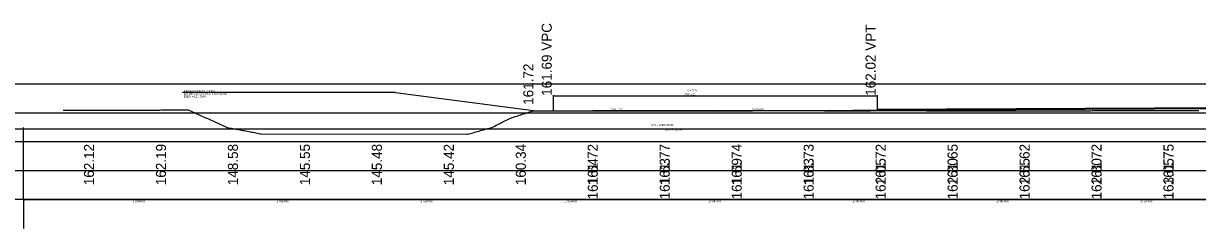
# Model space of a CAD drawing. Extents: x 2126510 to 2136144, y 865066 to 868066.
# Drawn here: x 2131523 to 2132339, y 867794 to 867936 of the extents above; entities that cross this region are included whole.
import ezdxf

# ---------------------------------------------------------------- set-up
doc = ezdxf.new("R2010")
doc.units = 0
for name, color, linetype in [('RD_EX_GuardRail', 7, 'Continuous'), ('RD_EX_H2O', 7, 'Continuous'), ('RD_EX_Misc', 7, 'Continuous'), ('RD_EX_UT', 7, 'Continuous')]:
    doc.layers.add(name, color=color, linetype=linetype)

msp = doc.modelspace()

# ---------------------------------------------------------------- linework, layer by layer
at = {"layer": 'RD_EX_GuardRail'}
for p, q in [((2135251.98, 867894.32), (2130671.73, 867894.32)), ((2133154.24, 867874.32), (2130671.73, 867874.32)), ((2135251.98, 867854.32), (2130671.73, 867854.32)), ((2135251.98, 867834.32), (2130671.73, 867834.32)), ((2135251.98, 867814.32), (2130671.73, 867814.32))]:
    msp.add_line(p, q, dxfattribs=at)
at = {"layer": 'RD_EX_H2O'}
for points in [[(2131550.47, 867876.38), (2131551.47, 867876.38), (2131552.47, 867876.38), (2131553.47, 867876.38), (2131554.47, 867876.38), (2131555.47, 867876.38), (2131556.47, 867876.38), (2131557.47, 867876.38), (2131558.47, 867876.38), (2131559.47, 867876.38), (2131560.47, 867876.38), (2131561.47, 867876.39), (2131562.47, 867876.39), (2131563.47, 867876.4), (2131564.47, 867876.4), (2131565.47, 867876.41), (2131566.47, 867876.41), (2131567.47, 867876.41), (2131568.47, 867876.42), (2131569.47, 867876.42), (2131570.47, 867876.43), (2131571.47, 867876.43), (2131572.47, 867876.44), (2131573.47, 867876.44), (2131574.47, 867876.45), (2131575.47, 867876.45), (2131576.47, 867876.45), (2131577.47, 867876.46), (2131578.47, 867876.46), (2131579.47, 867876.46), (2131580.47, 867876.46), (2131581.47, 867876.46), (2131582.47, 867876.46), (2131583.47, 867876.46), (2131584.47, 867876.46), (2131585.47, 867876.46), (2131586.47, 867876.46), (2131587.47, 867876.45), (2131588.47, 867876.45), (2131589.47, 867876.45), (2131590.47, 867876.45), (2131591.47, 867876.45), (2131592.47, 867876.45), (2131593.47, 867876.45), (2131594.47, 867876.45), (2131595.47, 867876.45), (2131596.47, 867876.46), (2131597.47, 867876.46), (2131598.47, 867876.46), (2131599.47, 867876.46), (2131600.47, 867876.47), (2131601.47, 867876.47), (2131602.47, 867876.47), (2131603.47, 867876.47), (2131604.47, 867876.47), (2131605.47, 867876.47), (2131606.47, 867876.47), (2131607.47, 867876.47), (2131608.47, 867876.47), (2131609.47, 867876.47), (2131610.47, 867876.47), (2131611.47, 867876.47), (2131612.47, 867876.48), (2131613.47, 867876.48), (2131614.47, 867876.48), (2131615.47, 867876.48), (2131616.47, 867876.48), (2131617.47, 867876.48), (2131618.47, 867876.49), (2131619.47, 867876.5), (2131620.47, 867876.5), (2131621.47, 867876.5), (2131622.47, 867876.5), (2131623.47, 867876.5), (2131624.47, 867876.5), (2131625.47, 867876.51), (2131626.47, 867876.51), (2131627.47, 867876.51), (2131628.47, 867876.51), (2131629.47, 867876.51), (2131630.47, 867876.51), (2131631.47, 867876.52), (2131632.47, 867876.52), (2131633.47, 867876.52), (2131634.47, 867876.52), (2131635.47, 867876.52), (2131636.47, 867876.52), (2131637.47, 867876.51), (2131638.47, 867876.06), (2131639.47, 867875.62), (2131640.47, 867875.17), (2131641.47, 867874.73), (2131642.47, 867874.28), (2131643.47, 867873.84), (2131644.47, 867873.39), (2131645.47, 867872.94), (2131646.47, 867872.5), (2131647.47, 867872.05), (2131648.47, 867871.6), (2131649.47, 867871.16), (2131650.47, 867870.71)], [(2131650.47, 867870.71), (2131651.47, 867870.26), (2131652.47, 867869.8), (2131653.47, 867869.34), (2131654.47, 867868.88), (2131655.47, 867868.41), (2131656.47, 867867.95), (2131657.47, 867867.5), (2131658.47, 867867.04), (2131659.47, 867866.59), (2131660.47, 867866.13), (2131661.47, 867865.68), (2131662.47, 867865.22), (2131663.47, 867864.77), (2131664.47, 867864.34), (2131665.47, 867864.16), (2131666.47, 867863.99), (2131667.47, 867863.81), (2131668.47, 867863.64), (2131669.47, 867863.46), (2131670.47, 867863.29), (2131671.47, 867863.13), (2131672.47, 867862.98), (2131673.47, 867862.82), (2131674.47, 867862.56), (2131675.47, 867862.37), (2131676.47, 867862.18), (2131677.47, 867862), (2131678.47, 867861.8), (2131679.47, 867861.6), (2131680.47, 867861.41), (2131681.47, 867861.21), (2131682.47, 867861.01), (2131683.47, 867860.81), (2131684.47, 867860.61), (2131685.47, 867860.42), (2131686.47, 867860.22), (2131687.47, 867860.02), (2131688, 867859.91), (2131830.92, 867859.72), (2131831.47, 867859.78), (2131832.47, 867859.93), (2131833.47, 867860.15), (2131834.47, 867860.44), (2131835.47, 867860.73), (2131836.47, 867861.02), (2131837.47, 867861.3), (2131838.47, 867861.59), (2131839.47, 867861.88), (2131840.47, 867862.17), (2131841.47, 867862.46), (2131842.47, 867862.75), (2131843.47, 867863.03), (2131844.47, 867863.32), (2131845.47, 867863.7), (2131846.47, 867863.94), (2131847.47, 867864.19), (2131848.47, 867864.44), (2131849.47, 867864.82), (2131850.47, 867865.36), (2131851.47, 867865.89), (2131852.47, 867866.43), (2131853.47, 867866.97), (2131854.47, 867867.45), (2131855.47, 867867.93), (2131856.47, 867868.4), (2131857.47, 867868.88), (2131858.47, 867869.35), (2131859.47, 867869.82), (2131860.47, 867870.3), (2131861.47, 867870.77), (2131862.47, 867871.23), (2131863.47, 867871.56), (2131864.47, 867871.88), (2131865.47, 867872.21), (2131866.47, 867872.53), (2131867.47, 867872.86), (2131868.47, 867873.18), (2131869.47, 867873.51), (2131870.47, 867873.83), (2131871.47, 867874.16), (2131872.47, 867874.48), (2131873.47, 867874.81), (2131874.47, 867875.13), (2131875.47, 867875.45), (2131876.47, 867875.78), (2131877.47, 867876.01), (2131878.47, 867876), (2131879.47, 867876), (2131880.47, 867876), (2131881.47, 867876), (2131882.47, 867876), (2131883.47, 867876), (2131884.47, 867876), (2131885.47, 867876), (2131886.47, 867876), (2131887.47, 867876), (2131888.47, 867875.99), (2131889.47, 867875.99), (2131890.47, 867875.99), (2131891.47, 867875.99)], [(2132091.47, 867875.98), (2132092.47, 867875.98), (2132093.47, 867875.99), (2132094.47, 867875.99), (2132095.47, 867875.99), (2132096.47, 867875.99), (2132097.47, 867875.99), (2132098.47, 867875.99), (2132099.47, 867875.99), (2132100.47, 867876), (2132101.47, 867876), (2132102.47, 867876), (2132103.47, 867876), (2132104.47, 867876), (2132105.47, 867876), (2132106.47, 867876), (2132107.47, 867876.01), (2132108.47, 867876.01), (2132109.47, 867876.01), (2132110.47, 867876.01), (2132111.47, 867876.01), (2132112.47, 867876.02), (2132113.47, 867876.02), (2132114.47, 867876.02), (2132115.47, 867876.02), (2132116.47, 867876.02), (2132117.47, 867876.02), (2132118.47, 867876.03), (2132119.47, 867876.03), (2132120.47, 867876.03), (2132121.47, 867876.03), (2132122.47, 867876.03), (2132123.47, 867876.04), (2132124.47, 867876.04), (2132125.47, 867876.04), (2132126.47, 867876.04), (2132127.47, 867876.04), (2132128.47, 867876.04), (2132129.47, 867876.04), (2132130.47, 867876.04), (2132131.47, 867876.04), (2132132.47, 867876.04), (2132133.47, 867876.04), (2132134.47, 867876.04), (2132135.47, 867876.04), (2132136.47, 867876.04), (2132137.47, 867876.03), (2132138.47, 867876.03), (2132139.47, 867876.03), (2132140.47, 867876.03), (2132141.47, 867876.03), (2132142.47, 867876.03), (2132143.47, 867876.03), (2132144.47, 867876.03), (2132145.47, 867876.03), (2132146.47, 867876.03), (2132147.47, 867876.02), (2132148.47, 867876.02), (2132149.47, 867876.02), (2132150.47, 867876.01), (2132151.47, 867876.01), (2132152.47, 867876.01), (2132153.47, 867876), (2132154.47, 867876), (2132155.47, 867876), (2132156.47, 867876), (2132157.47, 867875.99), (2132158.47, 867875.99), (2132159.47, 867875.99), (2132160.47, 867875.98), (2132161.47, 867875.98), (2132162.47, 867875.98), (2132163.47, 867875.98), (2132164.47, 867875.97), (2132165.47, 867875.97), (2132166.47, 867875.97), (2132167.47, 867875.96), (2132168.47, 867875.96), (2132169.47, 867875.96), (2132170.47, 867875.96), (2132171.47, 867875.97), (2132172.47, 867875.97), (2132173.47, 867875.97), (2132174.47, 867875.97), (2132175.47, 867875.97), (2132176.47, 867875.97), (2132177.47, 867875.97), (2132178.47, 867875.97), (2132179.47, 867875.97), (2132180.47, 867875.98), (2132181.47, 867875.98), (2132182.47, 867875.98), (2132183.47, 867875.98), (2132184.47, 867875.98), (2132185.47, 867875.98), (2132186.47, 867875.98), (2132187.47, 867875.99), (2132188.47, 867875.99), (2132189.47, 867875.98), (2132190.47, 867875.98), (2132191.47, 867875.98)], [(2132191.47, 867875.98), (2132192.47, 867875.98), (2132193.47, 867875.98), (2132194.47, 867875.98), (2132195.47, 867875.98), (2132196.47, 867875.97), (2132197.47, 867875.97), (2132198.47, 867875.97), (2132199.47, 867875.97), (2132200.47, 867875.97), (2132201.47, 867875.97), (2132202.47, 867875.97), (2132203.47, 867875.96), (2132204.47, 867875.96), (2132205.47, 867875.96), (2132206.47, 867875.96), (2132207.47, 867875.96), (2132208.47, 867875.96), (2132209.47, 867875.96), (2132210.47, 867875.96), (2132211.47, 867875.95), (2132212.47, 867875.95), (2132213.47, 867875.95), (2132214.47, 867875.95), (2132215.47, 867875.95), (2132216.47, 867875.94), (2132217.47, 867875.94), (2132218.47, 867875.94), (2132219.47, 867875.94), (2132220.47, 867875.94), (2132221.47, 867875.94), (2132222.47, 867875.93), (2132223.47, 867875.93), (2132224.47, 867875.93), (2132225.47, 867875.93), (2132226.47, 867875.93), (2132227.47, 867875.93), (2132228.47, 867875.93), (2132229.47, 867875.93), (2132230.47, 867875.93), (2132231.47, 867875.93), (2132232.47, 867875.93), (2132233.47, 867875.93), (2132234.47, 867875.92), (2132235.47, 867875.92), (2132236.47, 867875.92), (2132237.47, 867875.92), (2132238.47, 867875.92), (2132239.47, 867875.92), (2132240.47, 867875.92), (2132241.47, 867875.91), (2132242.47, 867875.91), (2132243.47, 867875.91), (2132244.47, 867875.91), (2132245.47, 867875.91), (2132246.47, 867875.92), (2132247.47, 867875.92), (2132248.47, 867875.93), (2132249.47, 867875.93), (2132250.47, 867875.94), (2132251.47, 867875.94), (2132252.47, 867875.94), (2132253.47, 867875.95), (2132254.47, 867875.95), (2132255.47, 867875.96), (2132256.47, 867875.96), (2132257.47, 867875.97), (2132258.47, 867875.97), (2132259.47, 867875.98), (2132260.47, 867875.98), (2132261.47, 867875.99), (2132262.47, 867875.99), (2132263.47, 867876), (2132264.47, 867876.01), (2132265.47, 867876.02), (2132266.47, 867876.02), (2132267.47, 867876.02), (2132268.47, 867876.02), (2132269.47, 867876.03), (2132270.47, 867876.03), (2132271.47, 867876.03), (2132272.47, 867876.03), (2132273.47, 867876.03), (2132274.47, 867876.04), (2132275.47, 867876.04), (2132276.47, 867876.04), (2132277.47, 867876.04), (2132278.47, 867876.04), (2132279.47, 867876.04), (2132280.47, 867876.05), (2132281.47, 867876.05), (2132282.47, 867876.05), (2132283.47, 867876.05), (2132284.47, 867876.05), (2132285.47, 867876.05), (2132286.47, 867876.05), (2132287.47, 867876.05), (2132288.47, 867876.04), (2132289.47, 867876.05), (2132290.47, 867876.06), (2132291.47, 867876.06)], [(2132291.47, 867876.06), (2132292.47, 867876.07), (2132293.47, 867876.07), (2132294.47, 867876.08), (2132295.47, 867876.09), (2132296.47, 867876.09), (2132297.47, 867876.1), (2132298.47, 867876.1), (2132299.47, 867876.11), (2132300.47, 867876.12), (2132301.47, 867876.12), (2132302.47, 867876.13), (2132303.47, 867876.13), (2132304.47, 867876.13), (2132305.47, 867876.13), (2132306.47, 867876.13), (2132307.47, 867876.13), (2132308.47, 867876.13), (2132309.47, 867876.12), (2132310.47, 867876.12), (2132311.47, 867876.11), (2132312.47, 867876.11), (2132313.47, 867876.1), (2132314.47, 867876.1), (2132315.47, 867876.09), (2132316.47, 867876.09), (2132317.47, 867876.08), (2132318.47, 867876.08), (2132319.47, 867876.07), (2132320.47, 867876.07), (2132321.47, 867876.06), (2132322.47, 867876.06), (2132323.47, 867876.07), (2132324.47, 867876.08), (2132325.47, 867876.08), (2132326.47, 867876.09), (2132327.47, 867876.09), (2132328.47, 867876.09), (2132329.47, 867876.1), (2132330.47, 867876.1), (2132331.47, 867876.1), (2132332.47, 867876.11), (2132333.47, 867876.11), (2132334.47, 867876.11), (2132335.47, 867876.11), (2132336.47, 867876.12), (2132337.47, 867876.12), (2132338.47, 867876.12), (2132339.47, 867876.12)]]:
    msp.add_lwpolyline(points, dxfattribs=at)
at = {"layer": 'RD_EX_Misc'}
for p, q in [((2131781.53, 867888.55), (2131633.39, 867888.55)), ((2131891.01, 867886.83), (2131891.01, 867876.01)), ((2131891.01, 867886.33), (2132116.01, 867886.33)), ((2132116.01, 867886.83), (2132116.01, 867876.33)), ((2132116.01, 867877.03), (2133296.65, 867882.93)), ((2131877.22, 867876.04), (2131891.01, 867876.01)), ((2131923.51, 867875.94), (2132003.51, 867875.77)), ((2132083.48, 867876.17), (2132003.51, 867875.77)), ((2131523, 867814.32), (2131523, 867864.32)), ((2131523, 867814.32), (2135677.25, 867814.32)), ((2131523, 867814.32), (2131523, 867794.32))]:
    msp.add_line(p, q, dxfattribs=at)
for points in [[(2131781.53, 867888.55), (2131877.22, 867876.04)], [(2131891.47, 867875.99), (2131892.47, 867875.99), (2131893.47, 867875.99), (2131894.47, 867875.99), (2131895.47, 867875.99), (2131896.47, 867875.99), (2131897.47, 867875.99), (2131898.47, 867875.99), (2131899.47, 867875.99), (2131900.47, 867875.99), (2131901.47, 867875.99), (2131902.47, 867875.98), (2131903.47, 867875.98), (2131904.47, 867875.98), (2131905.47, 867875.98), (2131906.47, 867875.98), (2131907.47, 867875.98), (2131908.47, 867875.98), (2131909.47, 867875.98), (2131910.47, 867875.99), (2131911.47, 867875.99), (2131912.47, 867875.99), (2131913.47, 867876), (2131914.47, 867876), (2131915.47, 867876), (2131916.47, 867876.01), (2131917.47, 867876.01), (2131918.47, 867876.02), (2131919.47, 867876.02), (2131920.47, 867876.02), (2131921.47, 867876.03), (2131922.47, 867876.03), (2131923.47, 867876.03), (2131924.47, 867876.04), (2131925.47, 867876.04), (2131926.47, 867876.04), (2131927.47, 867876.05), (2131928.47, 867876.05), (2131929.47, 867876.05), (2131930.47, 867876.05), (2131931.47, 867876.05), (2131932.47, 867876.05), (2131933.47, 867876.05), (2131934.47, 867876.06), (2131935.47, 867876.06), (2131936.47, 867876.06), (2131937.47, 867876.06), (2131938.47, 867876.06), (2131939.47, 867876.06), (2131940.47, 867876.06), (2131941.47, 867876.06), (2131942.47, 867876.06), (2131943.47, 867876.06), (2131944.47, 867876.06), (2131945.47, 867876.07), (2131946.47, 867876.07), (2131947.47, 867876.07), (2131948.47, 867876.07), (2131949.47, 867876.07), (2131950.47, 867876.07), (2131951.47, 867876.07), (2131952.47, 867876.07), (2131953.47, 867876.07), (2131954.47, 867876.07), (2131955.47, 867876.07), (2131956.47, 867876.07), (2131957.47, 867876.07), (2131958.47, 867876.08), (2131959.47, 867876.08), (2131960.47, 867876.08), (2131961.47, 867876.08), (2131962.47, 867876.08), (2131963.47, 867876.08), (2131964.47, 867876.08), (2131965.47, 867876.08), (2131966.47, 867876.08), (2131967.47, 867876.08), (2131968.47, 867876.08), (2131969.47, 867876.08), (2131970.47, 867876.08), (2131971.47, 867876.08), (2131972.47, 867876.08), (2131973.47, 867876.08), (2131974.47, 867876.08), (2131975.47, 867876.08), (2131976.47, 867876.08), (2131977.47, 867876.08), (2131978.47, 867876.08), (2131979.47, 867876.08), (2131980.47, 867876.08), (2131981.47, 867876.08), (2131982.47, 867876.08), (2131983.47, 867876.08), (2131984.47, 867876.08), (2131985.47, 867876.08), (2131986.47, 867876.08), (2131987.47, 867876.08), (2131988.47, 867876.08), (2131989.47, 867876.08), (2131990.47, 867876.08), (2131991.47, 867876.08)], [(2131991.47, 867876.08), (2131992.47, 867876.07), (2131993.47, 867876.07), (2131994.47, 867876.07), (2131995.47, 867876.07), (2131996.47, 867876.07), (2131997.47, 867876.06), (2131998.47, 867876.06), (2131999.47, 867876.06), (2132000.47, 867876.06), (2132001.47, 867876.06), (2132002.47, 867876.06), (2132003.47, 867876.05), (2132004.47, 867876.05), (2132005.47, 867876.05), (2132006.47, 867876.05), (2132007.47, 867876.05), (2132008.47, 867876.04), (2132009.47, 867876.04), (2132010.47, 867876.04), (2132011.47, 867876.04), (2132012.47, 867876.05), (2132013.47, 867876.05), (2132014.47, 867876.05), (2132015.47, 867876.05), (2132016.47, 867876.05), (2132017.47, 867876.05), (2132018.47, 867876.05), (2132019.47, 867876.05), (2132020.47, 867876.05), (2132021.47, 867876.05), (2132022.47, 867876.05), (2132023.47, 867876.06), (2132024.47, 867876.06), (2132025.47, 867876.06), (2132026.47, 867876.06), (2132027.47, 867876.06), (2132028.47, 867876.06), (2132029.47, 867876.06), (2132030.47, 867876.06), (2132031.47, 867876.06), (2132032.47, 867876.06), (2132033.47, 867876.06), (2132034.47, 867876.07), (2132035.47, 867876.07), (2132036.47, 867876.07), (2132037.47, 867876.07), (2132038.47, 867876.07), (2132039.47, 867876.08), (2132040.47, 867876.08), (2132041.47, 867876.08), (2132042.47, 867876.08), (2132043.47, 867876.08), (2132044.47, 867876.08), (2132045.47, 867876.08), (2132046.47, 867876.09), (2132047.47, 867876.09), (2132048.47, 867876.09), (2132049.47, 867876.09), (2132050.47, 867876.09), (2132051.47, 867876.09), (2132052.47, 867876.09), (2132053.47, 867876.09), (2132054.47, 867876.09), (2132055.47, 867876.09), (2132056.47, 867876.08), (2132057.47, 867876.08), (2132058.47, 867876.08), (2132059.47, 867876.08), (2132060.47, 867876.08), (2132061.47, 867876.08), (2132062.47, 867876.08), (2132063.47, 867876.08), (2132064.47, 867876.07), (2132065.47, 867876.07), (2132066.47, 867876.07), (2132067.47, 867876.07), (2132068.47, 867876.07), (2132069.47, 867876.06), (2132070.47, 867876.06), (2132071.47, 867876.05), (2132072.47, 867876.05), (2132073.47, 867876.04), (2132074.47, 867876.04), (2132075.47, 867876.03), (2132076.47, 867876.03), (2132077.47, 867876.02), (2132078.47, 867876.02), (2132079.47, 867876.01), (2132080.47, 867876.01), (2132081.47, 867876), (2132082.47, 867876), (2132083.47, 867875.99), (2132084.47, 867875.99), (2132085.47, 867875.98), (2132086.47, 867875.98), (2132087.47, 867875.98), (2132088.47, 867875.98), (2132089.47, 867875.98), (2132090.47, 867875.98), (2132091.47, 867875.98)], [(2131430.13, 867814.32), (2131430.13, 867863.32), (2136143.96, 867863.32)]]:
    msp.add_lwpolyline(points, dxfattribs=at)
msp.add_spline([(2131891.01, 867876.01), (2131895.51, 867876), (2131900.01, 867875.99), (2131904.51, 867875.98), (2131909.01, 867875.97), (2131913.51, 867875.97), (2131918.01, 867875.96), (2131922.51, 867875.96), (2131927.01, 867875.95), (2131931.51, 867875.95), (2131936.01, 867875.94), (2131940.51, 867875.94), (2131945.01, 867875.94), (2131949.51, 867875.94), (2131954.01, 867875.94), (2131958.51, 867875.94), (2131963.01, 867875.94), (2131967.51, 867875.94), (2131972.01, 867875.94), (2131976.51, 867875.94), (2131981.01, 867875.95), (2131985.51, 867875.95), (2131990.01, 867875.95), (2131994.51, 867875.96), (2131999.01, 867875.96), (2132003.51, 867875.97), (2132008.01, 867875.98), (2132012.51, 867875.99), (2132017.01, 867875.99), (2132021.51, 867876), (2132026.01, 867876.01), (2132030.51, 867876.02), (2132035.01, 867876.03), (2132039.51, 867876.04), (2132044.01, 867876.06), (2132048.51, 867876.07), (2132053.01, 867876.08), (2132057.51, 867876.1), (2132062.01, 867876.11), (2132066.51, 867876.13), (2132071.01, 867876.14), (2132075.51, 867876.16), (2132080.01, 867876.17), (2132084.51, 867876.19), (2132089.01, 867876.21), (2132093.51, 867876.23), (2132098.01, 867876.25), (2132102.51, 867876.27), (2132107.01, 867876.29), (2132111.51, 867876.31), (2132116.01, 867876.33)], degree=3, dxfattribs=at)
at = {"layer": 'RD_EX_UT'}
msp.add_line((2132116.01, 867876.33), (2133296.65, 867882.24), dxfattribs=at)

# ---------------------------------------------------------------- texts
at = {"layer": 'RD_EX_Misc'}
for s, height, rotation, p in [('161.69 VPC', 7, 90, (2131890.01, 867886.33)), ('162.02 VPT', 7, 90, (2132115.01, 867886.33)), ('161.72', 7, 90, (2131877.22, 867880.04)), ('(-) 0.21%', 1.402, 359.88053, (2131931.21, 867876.32)), ('(+) 0.50%', 1.41, 0.28648, (2132029.12, 867876.3)), ('162.12', 7, 90, (2131572, 867824.32)), ('162.19', 7, 90, (2131622, 867824.32)), ('148.58', 7, 90, (2131672, 867824.32)), ('145.55', 7, 90, (2131722, 867824.32)), ('145.48', 7, 90, (2131772, 867824.32)), ('145.42', 7, 90, (2131822, 867824.32)), ('160.34', 7, 90, (2131872, 867824.32)), ('161.72', 7, 90, (2131922, 867824.32)), ('161.77', 7, 90, (2131972, 867824.32)), ('161.74', 7, 90, (2132022, 867824.32)), ('161.73', 7, 90, (2132072, 867824.32)), ('161.72', 7, 90, (2132122, 867824.32)), ('161.65', 7, 90, (2132172, 867824.32)), ('161.62', 7, 90, (2132222, 867824.32)), ('161.72', 7, 90, (2132272, 867824.32)), ('161.75', 7, 90, (2132322, 867824.32)), ('161.64', 7, 90, (2131922, 867814.47)), ('161.63', 7, 90, (2131972, 867814.47)), ('161.69', 7, 90, (2132022, 867814.47)), ('161.83', 7, 90, (2132072, 867814.47)), ('162.05', 7, 90, (2132122, 867814.47)), ('162.30', 7, 90, (2132172, 867814.47)), ('162.55', 7, 90, (2132222, 867814.47)), ('162.80', 7, 90, (2132272, 867814.47)), ('163.05', 7, 90, (2132322, 867814.47))]:
    msp.add_text(s, height=height, rotation=rotation, dxfattribs=at).set_placement(p)
for s, height, p in [('BEGIN CONSTRUCTION', 1.4, (2131634.39, 867888.75)), ('I20_EB_CONST STA. 1792+55.00', 1.4, (2131634.39, 867886.95)), ("225' V.C.", 1.4, (2131982.25, 867886.58)), ('K = 318', 1.4, (2131983.95, 867889.38)), ('ELEV = 161.7200', 1.4, (2131634.39, 867885.15)), ('VPI = 1793+80.51', 1.4, (2131959.03, 867865.37)), ('Elev. = 161.46', 1.4, (2131968.45, 867862.37)), ('I20', 0.0417, (2131523, 867815.19)), ('I20_EB_CONST', 0.0417, (2131523, 867815.07)), ('178900.000000', 0.0417, (2131523, 867814.94)), ('100', 0.0417, (2131523, 867814.82)), ('50', 0.0417, (2131523, 867814.69)), ('10', 0.0417, (2131523, 867814.57)), ('NOGAP', 0.0417, (2131523, 867814.44)), ('1790+00', 1.6, (2131598.79, 867812.52)), ('1791+00', 1.6, (2131698.79, 867812.52)), ('1792+00', 1.6, (2131798.79, 867812.52)), ('1793+00', 1.6, (2131898.79, 867812.52)), ('1794+00', 1.6, (2131998.79, 867812.52)), ('1795+00', 1.6, (2132098.79, 867812.52)), ('1796+00', 1.6, (2132198.79, 867812.52)), ('1797+00', 1.6, (2132298.79, 867812.52))]:
    msp.add_text(s, height=height, dxfattribs=at).set_placement(p)

doc.saveas('drawing.dxf')
